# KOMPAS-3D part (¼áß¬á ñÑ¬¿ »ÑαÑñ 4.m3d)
File: created 06.04.2016 12:01:11, last saved 22.07.2016 16:03:26.
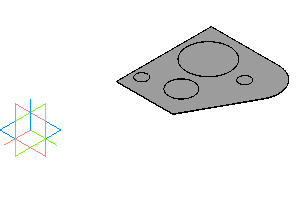
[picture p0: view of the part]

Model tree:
1. Эскиз:1
2. Операция выдавливания:1
     Толщина стенки 2 = 15; Расстояние 1 = 0.8; Расстояние 2 = 96.2519
3. Эскиз:2
4. Вырезать элемент выдавливания:1
     Толщина стенки 1 = 2; Толщина стенки 2 = 2; Расстояние 1 = 10
5. Эскиз:3
6. Вырезать элемент выдавливания:2
     Толщина стенки 1 = 2; Толщина стенки 2 = 2; Расстояние 1 = 10
7. Эскиз:4
8. Вырезать элемент выдавливания:3
     Толщина стенки 1 = 2; Толщина стенки 2 = 2; Расстояние 1 = 10
9. Эскиз:5
10. Вырезать элемент выдавливания:4
     Толщина стенки 1 = 2; Толщина стенки 2 = 2; Расстояние 1 = 0.4
11. Эскиз:6
12. Вырезать элемент выдавливания:5
     Толщина стенки 1 = 2; Толщина стенки 2 = 2; Расстояние 1 = 0.4
13. Эскиз:7
14. Вырезать элемент выдавливания:6
     Толщина стенки 1 = 2; Толщина стенки 2 = 2; Расстояние 1 = 10.4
